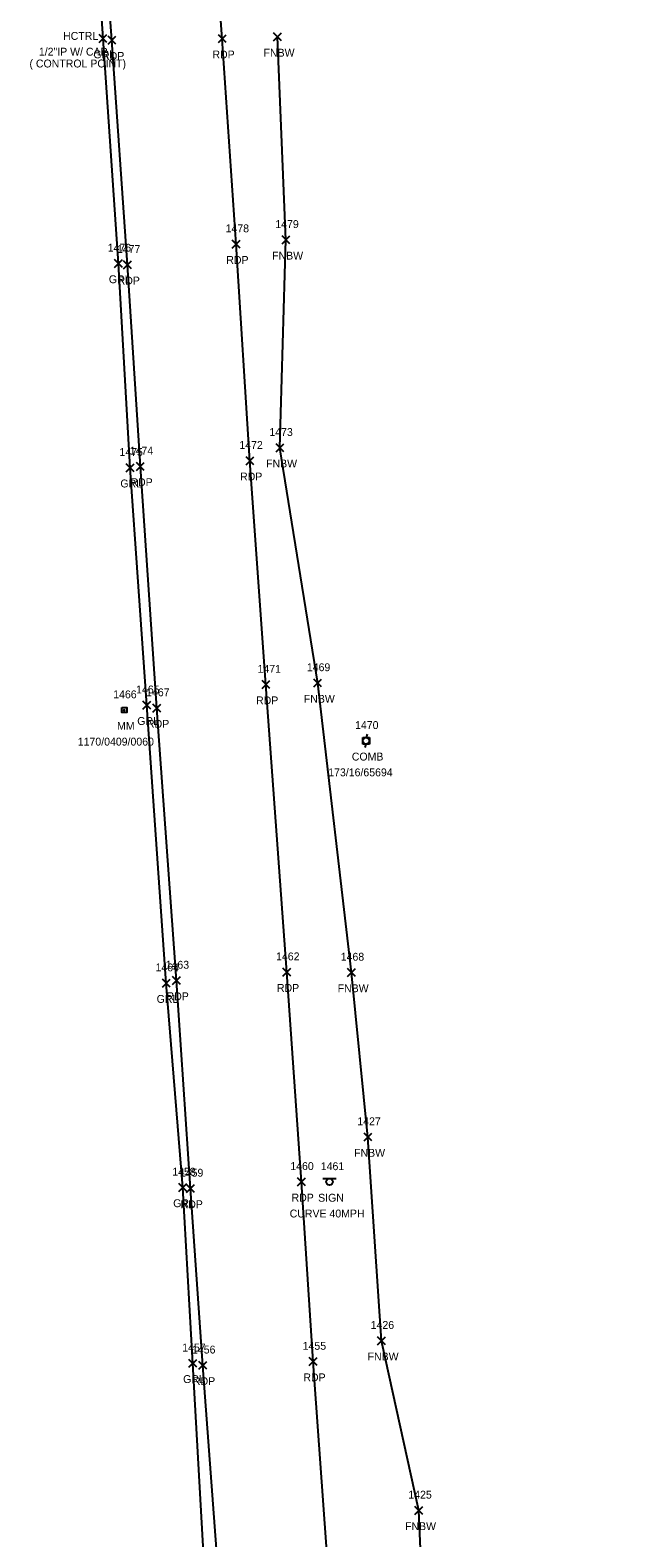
# Model space of a CAD drawing. Extents: x 1503463 to 1505240, y 712171 to 717196.
# Drawn here: x 1503509.3 to 1503661.3, y 716279.6 to 716662.1 of the extents above; entities that cross this region are included whole.
import ezdxf

# ---------------------------------------------------------------- set-up
doc = ezdxf.new("R2010")
doc.units = 0
for name, color, linetype in [('C_A', 7, 'Continuous'), ('C_C', 7, 'Continuous'), ('L_A', 7, 'Continuous'), ('L_I', 7, 'Continuous'), ('L_TIC', 7, 'Continuous'), ('LFNC', 7, 'Continuous'), ('P_A', 7, 'Continuous'), ('P_I', 7, 'Continuous'), ('P_TIC', 7, 'Continuous'), ('PET', 7, 'Continuous'), ('R_A', 7, 'Continuous'), ('R_I', 7, 'Continuous'), ('R_TIC', 7, 'Continuous'), ('RGR', 7, 'Continuous'), ('S_A', 7, 'Continuous'), ('S_C', 7, 'Continuous'), ('S_I', 7, 'Continuous'), ('SRM', 7, 'Continuous'), ('SSGN', 7, 'Continuous'), ('U_A', 7, 'Continuous'), ('U_C', 7, 'Continuous'), ('U_I', 7, 'Continuous'), ('UP', 7, 'Continuous')]:
    doc.layers.add(name, color=color, linetype=linetype)

msp = doc.modelspace()

# ---------------------------------------------------------------- linework, layer by layer
at = {"layer": 'L_TIC'}
for points in [[(1503571.12, 716659.4), (1503573.12, 716661.4)], [(1503573.12, 716659.4), (1503571.12, 716661.4)], [(1503573.28, 716607.92), (1503575.28, 716609.92)], [(1503575.28, 716607.92), (1503573.28, 716609.92)], [(1503571.76, 716555.17), (1503573.76, 716557.17)], [(1503573.76, 716555.17), (1503571.76, 716557.17)], [(1503581.34, 716495.49), (1503583.34, 716497.49)], [(1503583.34, 716495.49), (1503581.34, 716497.49)], [(1503589.93, 716422.05), (1503591.93, 716424.05)], [(1503591.93, 716422.05), (1503589.93, 716424.05)], [(1503594.1, 716380.31), (1503596.1, 716382.31)], [(1503596.1, 716380.31), (1503594.1, 716382.31)], [(1503597.54, 716328.63), (1503599.54, 716330.63)], [(1503599.54, 716328.63), (1503597.54, 716330.63)], [(1503607.04, 716285.58), (1503609.04, 716287.58)], [(1503609.04, 716285.58), (1503607.04, 716287.58)]]:
    msp.add_lwpolyline(points, dxfattribs=at)
at = {"layer": 'LFNC'}
msp.add_lwpolyline([(1503661.34, 715848.63), (1503646.28, 715894.79), (1503638.89, 715915.64), (1503642.5, 715935.56), (1503650.4, 715942.12), (1503650.47, 715957.43), (1503642.13, 715980.34), (1503635.04, 716030.34), (1503633.5, 716067.12), (1503626.36, 716116.24), (1503614.98, 716149.58), (1503614.84, 716190.52), (1503610.52, 716227.96), (1503608.04, 716286.58), (1503598.54, 716329.63), (1503595.1, 716381.31), (1503590.93, 716423.05), (1503582.34, 716496.49), (1503572.76, 716556.17), (1503574.28, 716608.92), (1503572.12, 716660.4)], dxfattribs=at)
at = {"layer": 'P_TIC'}
for points in [[(1503557.12, 716658.95), (1503559.12, 716660.95)], [(1503559.12, 716658.95), (1503557.12, 716660.95)], [(1503529.11, 716658.58), (1503531.11, 716660.58)], [(1503531.11, 716658.58), (1503529.11, 716660.58)], [(1503560.64, 716606.83), (1503562.64, 716608.83)], [(1503562.64, 716606.83), (1503560.64, 716608.83)], [(1503533.05, 716601.59), (1503535.05, 716603.59)], [(1503535.05, 716601.59), (1503533.05, 716603.59)], [(1503564.14, 716551.88), (1503566.14, 716553.88)], [(1503566.14, 716551.88), (1503564.14, 716553.88)], [(1503536.31, 716550.44), (1503538.31, 716552.44)], [(1503538.31, 716550.44), (1503536.31, 716552.44)], [(1503568.2, 716495.09), (1503570.2, 716497.09)], [(1503570.2, 716495.09), (1503568.2, 716497.09)], [(1503540.51, 716489.14), (1503542.51, 716491.14)], [(1503542.51, 716489.14), (1503540.51, 716491.14)], [(1503573.51, 716422.14), (1503575.51, 716424.14)], [(1503575.51, 716422.14), (1503573.51, 716424.14)], [(1503545.48, 716420.02), (1503547.48, 716422.02)], [(1503547.48, 716420.02), (1503545.48, 716422.02)], [(1503577.21, 716368.94), (1503579.21, 716370.94)], [(1503579.21, 716368.94), (1503577.21, 716370.94)], [(1503549.05, 716367.26), (1503551.05, 716369.26)], [(1503551.05, 716367.26), (1503549.05, 716369.26)], [(1503552.18, 716322.39), (1503554.18, 716324.39)], [(1503554.18, 716322.39), (1503552.18, 716324.39)], [(1503580.21, 716323.34), (1503582.21, 716325.34)], [(1503582.21, 716323.34), (1503580.21, 716325.34)]]:
    msp.add_lwpolyline(points, dxfattribs=at)
at = {"layer": 'PET'}
for points in [[(1503620.07, 715849.48), (1503602.71, 715905.3), (1503591.6, 715950.55), (1503581.96, 716002.91), (1503575.08, 716054.31), (1503570.5, 716102.59), (1503565.74, 716154.6), (1503561.01, 716212.19), (1503557.24, 716268.87), (1503553.18, 716323.39), (1503550.05, 716368.26), (1503546.48, 716421.02), (1503541.51, 716490.14), (1503537.31, 716551.44), (1503534.05, 716602.59), (1503530.11, 716659.58), (1503525.62, 716720.04)], [(1503646.76, 715858.44), (1503630.24, 715911.59), (1503619.37, 715956.88), (1503610.29, 716006.85), (1503602.92, 716056.6), (1503598.34, 716105.6), (1503593.12, 716157.22), (1503588.93, 716213.58), (1503584.94, 716272.68), (1503581.21, 716324.34), (1503578.21, 716369.94), (1503574.51, 716423.14), (1503569.2, 716496.09), (1503565.14, 716552.88), (1503561.64, 716607.83), (1503558.12, 716659.95), (1503553.68, 716721.47)]]:
    msp.add_lwpolyline(points, dxfattribs=at)
at = {"layer": 'R_TIC'}
for points in [[(1503526.84, 716658.98), (1503528.84, 716660.98)], [(1503528.84, 716658.98), (1503526.84, 716660.98)], [(1503530.77, 716601.92), (1503532.77, 716603.92)], [(1503532.77, 716601.92), (1503530.77, 716603.92)], [(1503533.7, 716550.11), (1503535.7, 716552.11)], [(1503535.7, 716550.11), (1503533.7, 716552.11)], [(1503537.97, 716489.86), (1503539.97, 716491.86)], [(1503539.97, 716489.86), (1503537.97, 716491.86)], [(1503542.9, 716419.35), (1503544.9, 716421.35)], [(1503544.9, 716419.35), (1503542.9, 716421.35)], [(1503547.1, 716367.52), (1503549.1, 716369.52)], [(1503549.1, 716367.52), (1503547.1, 716369.52)], [(1503549.62, 716322.9), (1503551.62, 716324.9)], [(1503551.62, 716322.9), (1503549.62, 716324.9)]]:
    msp.add_lwpolyline(points, dxfattribs=at)
at = {"layer": 'RGR'}
msp.add_lwpolyline([(1503619.03, 715849.2), (1503601.73, 715905.18), (1503590.42, 715950.28), (1503580.77, 716002.98), (1503573.84, 716054.53), (1503568.88, 716102.71), (1503562.74, 716154), (1503557.41, 716213.15), (1503553.78, 716268.47), (1503550.62, 716323.9), (1503548.1, 716368.52), (1503543.9, 716420.35), (1503538.97, 716490.86), (1503534.7, 716551.11), (1503531.77, 716602.92), (1503527.84, 716659.98), (1503523.83, 716719.82)], dxfattribs=at)
at = {"layer": 'SRM'}
msp.add_lwpolyline([(1503532.59, 716490.25), (1503533.84, 716490.25), (1503533.84, 716489), (1503532.59, 716489)], close=True, dxfattribs=at)
msp.add_circle((1503533.21, 716489.62), 0.0833, dxfattribs=at)
at = {"layer": 'SSGN'}
for p, q in [((1503583.67, 716370.76), (1503587, 716370.76)), ((1503585.31, 716369.93), (1503585.31, 716369.93))]:
    msp.add_line(p, q, dxfattribs=at)
msp.add_circle((1503585.31, 716369.93), 0.833, dxfattribs=at)
at = {"layer": 'UP'}
for p, q in [((1503593.78, 716481), (1503593.78, 716482.67)), ((1503593.78, 716482.67), (1503595.45, 716482.67)), ((1503594.86, 716483.5), (1503594.61, 716482.67)), ((1503594.61, 716481.83), (1503594.61, 716481.83)), ((1503595.45, 716482.67), (1503595.45, 716481)), ((1503595.45, 716481), (1503593.78, 716481)), ((1503594.36, 716480.17), (1503594.61, 716481))]:
    msp.add_line(p, q, dxfattribs=at)
msp.add_circle((1503594.61, 716481.83), 0.833, dxfattribs=at)

# ---------------------------------------------------------------- texts
at = {"layer": 'C_A'}
msp.add_text('HCTRL', height=2, dxfattribs=at).set_placement((1503517.69, 716659.66))
at = {"layer": 'C_C'}
for s, p in [('1/2"IP W/ CAP', (1503511.54, 716655.66)), ('( CONTROL POINT)', (1503509.16, 716652.66))]:
    msp.add_text(s, height=2, dxfattribs=at).set_placement(p)
at = {"layer": 'L_A'}
for p in [(1503568.59, 716655.4), (1503570.76, 716603.92), (1503569.23, 716551.17), (1503578.81, 716491.49), (1503587.4, 716418.05), (1503591.57, 716376.31), (1503595.01, 716324.63), (1503604.51, 716281.58)]:
    msp.add_text('FNBW', height=2, dxfattribs=at).set_placement(p)
at = {"layer": 'L_I'}
for s, p in [('1479', (1503571.58, 716611.92)), ('1473', (1503570.07, 716559.17)), ('1469', (1503579.59, 716499.49)), ('1468', (1503588.19, 716426.05)), ('1427', (1503592.4, 716384.31)), ('1426', (1503595.79, 716332.63)), ('1425', (1503605.35, 716289.58))]:
    msp.add_text(s, height=2, dxfattribs=at).set_placement(p)
at = {"layer": 'P_A'}
for p in [(1503527.59, 716654.58), (1503555.61, 716654.95), (1503559.13, 716602.83), (1503531.54, 716597.59), (1503534.79, 716546.44), (1503562.63, 716547.88), (1503566.69, 716491.09), (1503539, 716485.14), (1503571.99, 716418.14), (1503543.96, 716416.02), (1503575.69, 716364.94), (1503547.53, 716363.26), (1503578.7, 716319.34), (1503550.66, 716318.39)]:
    msp.add_text('RDP', height=2, dxfattribs=at).set_placement(p)
at = {"layer": 'P_I'}
for s, p in [('1478', (1503558.95, 716610.83)), ('1477', (1503531.36, 716605.59)), ('1472', (1503562.45, 716555.88)), ('1474', (1503534.61, 716554.44)), ('1471', (1503567.07, 716499.09)), ('1467', (1503538.77, 716493.14)), ('1462', (1503571.77, 716426.14)), ('1463', (1503543.74, 716424.02)), ('1460', (1503575.38, 716372.94)), ('1459', (1503547.35, 716371.26)), ('1456', (1503550.43, 716326.39)), ('1455', (1503578.52, 716327.34))]:
    msp.add_text(s, height=2, dxfattribs=at).set_placement(p)
at = {"layer": 'R_A'}
for p in [(1503525.38, 716654.98), (1503529.31, 716597.92), (1503532.24, 716546.11), (1503536.52, 716485.86), (1503541.44, 716415.35), (1503545.65, 716363.52), (1503548.17, 716318.9)]:
    msp.add_text('GRL', height=2, dxfattribs=at).set_placement(p)
at = {"layer": 'R_I'}
for s, p in [('1476', (1503529.02, 716605.92)), ('1475', (1503532.01, 716554.11)), ('1465', (1503536.23, 716493.86)), ('1464', (1503541.16, 716423.35)), ('1458', (1503545.41, 716371.52)), ('1457', (1503547.93, 716326.9))]:
    msp.add_text(s, height=2, dxfattribs=at).set_placement(p)
at = {"layer": 'S_A'}
for s, p in [('MM', (1503531.4, 716484.62)), ('SIGN', (1503582.45, 716364.91))]:
    msp.add_text(s, height=2, dxfattribs=at).set_placement(p)
at = {"layer": 'S_C'}
for s, p in [('1170/0409/0060', (1503521.42, 716480.62)), ('CURVE 40MPH', (1503575.22, 716360.91))]:
    msp.add_text(s, height=2, dxfattribs=at).set_placement(p)
at = {"layer": 'S_I'}
for s, p in [('1466', (1503530.42, 716492.62)), ('1461', (1503583.12, 716372.91))]:
    msp.add_text(s, height=2, dxfattribs=at).set_placement(p)
at = {"layer": 'U_A'}
msp.add_text('COMB', height=2, dxfattribs=at).set_placement((1503591, 716476.83))
at = {"layer": 'U_C'}
msp.add_text('173/16/65694', height=2, dxfattribs=at).set_placement((1503585.01, 716472.83))
at = {"layer": 'U_I'}
msp.add_text('1470', height=2, dxfattribs=at).set_placement((1503591.83, 716484.83))

doc.saveas('drawing.dxf')
